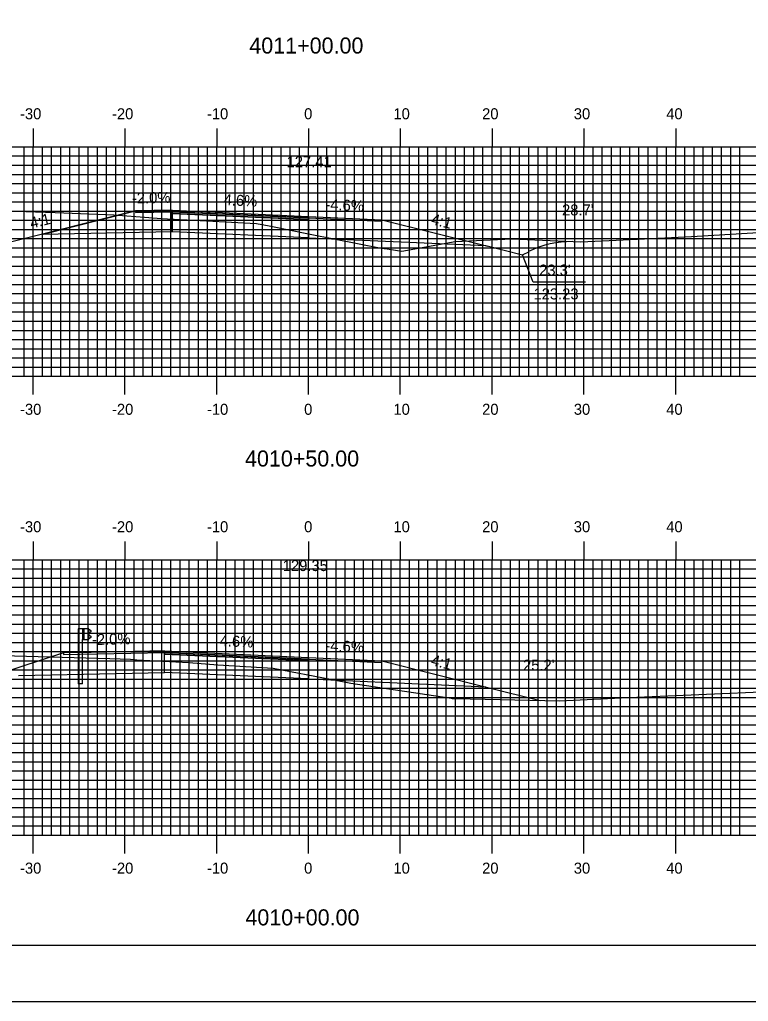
# Model space of a CAD drawing. Extents: x 852540 to 852884, y 364661 to 364881.
# Drawn here: x 852674.8 to 852754.2, y 364661.3 to 364768.2 of the extents above; entities that cross this region are included whole.
import ezdxf

# ---------------------------------------------------------------- set-up
doc = ezdxf.new("R2010")
doc.units = 0
for name, color, linetype in [('ANNOTATION', 7, 'Continuous'), ('BORDER', 7, 'Continuous'), ('D_Guardrail_Beam_Lt', 7, 'Continuous'), ('D_Roadway_Centerline_Text', 7, 'Continuous'), ('D_Roadway_Edge_Shoulder', 7, 'Continuous'), ('D_Roadway_Edge_TW', 7, 'Continuous'), ('D_Roadway_Pavement', 7, 'Continuous'), ('D_Roadway_SlopeLines', 7, 'Continuous'), ('D_Roadway_SubGrade', 7, 'Continuous'), ('D_Text_Standard', 7, 'Continuous'), ('H_V ANNOTATION', 7, 'Continuous'), ('M_Roadway_Centerline', 7, 'Continuous'), ('MAJOR', 7, 'Continuous'), ('MINOR', 7, 'Continuous'), ('PLOT BOUNDARY', 7, 'Continuous'), ('S_Roadway_Centerline', 7, 'Continuous')]:
    doc.layers.add(name, color=color, linetype=linetype)

msp = doc.modelspace()

# ---------------------------------------------------------------- linework, layer by layer
at = {"layer": 'ANNOTATION'}
for points in [[(852725.57, 364743.6), (852729.57, 364742.6), (852730.34, 364742.98)], [(852736.43, 364739.61), (852730.74, 364739.61), (852729.57, 364742.6)]]:
    msp.add_lwpolyline(points, dxfattribs=at)
at = {"layer": 'BORDER'}
msp.add_lwpolyline([(852556.67, 364667.37), (852876.67, 364667.37), (852876.67, 364877.37), (852556.67, 364877.37)], close=True, dxfattribs=at)
at = {"layer": 'D_Guardrail_Beam_Lt'}
for p, q in [((852681.16, 364701.86), (852681.16, 364695.86)), ((852681.63, 364701.86), (852681.16, 364701.86)), ((852682.32, 364701.86), (852681.63, 364701.86)), ((852681.63, 364701.86), (852681.63, 364700.7)), ((852681.69, 364701.86), (852681.69, 364700.7)), ((852681.8, 364701.86), (852681.8, 364700.7)), ((852682.32, 364700.7), (852682.32, 364701.86)), ((852682.32, 364701.78), (852682.39, 364701.77)), ((852682.32, 364701.32), (852682.32, 364701.25)), ((852682.55, 364701.52), (852682.35, 364701.38)), ((852682.35, 364701.18), (852682.55, 364701.05)), ((852682.41, 364701.76), (852682.55, 364701.66)), ((852682.55, 364700.9), (852682.41, 364700.8)), ((852681.63, 364700.7), (852682.32, 364700.7)), ((852681.65, 364695.86), (852681.65, 364700.7)), ((852682.39, 364700.8), (852682.32, 364700.78)), ((852681.65, 364695.86), (852681.16, 364695.86))]:
    msp.add_line(p, q, dxfattribs=at)
for centre, major_axis, start_param, end_param in [((852682.4, 364701.32), (-0.0789, 0), 5.323254, 6.283185), ((852682.4, 364701.25), (-0.0789, 0), 6.283185, 7.243116), ((852682.38, 364701.73), (0.0417, 0), 0.959931, 1.376053), ((852682.5, 364701.59), (0.0877, 0), 5.323254, 7.243116), ((852682.5, 364700.97), (0.0877, 0), 5.323254, 7.243116), ((852682.38, 364700.84), (0.0417, 0), 4.907132, 5.323254)]:
    msp.add_ellipse(centre, major_axis=major_axis, ratio=0.995501, start_param=start_param, end_param=end_param, dxfattribs=at)
at = {"layer": 'D_Roadway_Edge_Shoulder'}
for points in [[(852691.43, 364747.47), (852687.43, 364747.39), (852687.43, 364747.22), (852691.43, 364747.28)], [(852690.59, 364699.44), (852682.59, 364699.28), (852682.59, 364699.28), (852679.59, 364699.22), (852679.59, 364699.05), (852690.59, 364699.25)]]:
    msp.add_lwpolyline(points, close=True, dxfattribs=at)
at = {"layer": 'D_Roadway_Edge_TW'}
for p, q in [((852706.27, 364746.79), (852714.27, 364746.42)), ((852706.27, 364698.72), (852714.27, 364698.35))]:
    msp.add_line(p, q, dxfattribs=at)
for points in [[(852691.43, 364747.47), (852706.27, 364746.79), (852706.27, 364746.62), (852691.43, 364747.28)], [(852690.59, 364699.44), (852706.27, 364698.72), (852706.27, 364698.55), (852690.59, 364699.25)]]:
    msp.add_lwpolyline(points, close=True, dxfattribs=at)
for points in [[(852706.27, 364746.62), (852714.27, 364746.25), (852714.27, 364746.42)], [(852706.27, 364698.55), (852714.27, 364698.19), (852714.27, 364698.35)]]:
    msp.add_lwpolyline(points, dxfattribs=at)
at = {"layer": 'D_Roadway_Pavement'}
for points in [[(852691.43, 364747.28), (852706.27, 364746.62), (852706.27, 364746.46), (852691.43, 364747.12)], [(852690.59, 364699.25), (852706.27, 364698.55), (852706.27, 364698.39), (852690.59, 364699.09)]]:
    msp.add_lwpolyline(points, close=True, dxfattribs=at)
for points in [[(852691.43, 364747.28), (852691.43, 364747.12)], [(852706.27, 364746.62), (852706.27, 364746.46)], [(852706.27, 364746.62), (852706.27, 364746.46)], [(852690.59, 364699.25), (852690.59, 364699.09)], [(852706.27, 364698.55), (852706.27, 364698.39)], [(852706.27, 364698.55), (852706.27, 364698.39)]]:
    msp.add_lwpolyline(points, dxfattribs=at)
at = {"layer": 'D_Roadway_SlopeLines'}
for p, q in [((852679.59, 364699.22), (852636.79, 364685.3)), ((852674.67, 364696.76), (852690.59, 364697.09))]:
    msp.add_line(p, q, dxfattribs=at)
for points in [[(852687.43, 364747.39), (852673.2, 364743.83)], [(852714.27, 364746.42), (852725.8, 364743.54)], [(852714.27, 364698.35), (852725.8, 364695.47), (852731.5, 364694.04)]]:
    msp.add_lwpolyline(points, dxfattribs=at)
msp.add_arc((852734.82, 364734.04), 10, 89.0065, 116.5651, dxfattribs=at)
at = {"layer": 'D_Roadway_SubGrade'}
for p, q in [((852706.27, 364744.46), (852725.57, 364743.6)), ((852706.27, 364696.39), (852725.57, 364695.53))]:
    msp.add_line(p, q, dxfattribs=at)
for points in [[(852691.43, 364745.12), (852677.2, 364744.83), (852687.43, 364747.39), (852687.43, 364747.22), (852691.43, 364747.28), (852691.43, 364747.12)], [(852691.43, 364747.12), (852706.27, 364746.46), (852706.27, 364744.46), (852691.43, 364745.12)], [(852690.59, 364699.09), (852706.27, 364698.39), (852706.27, 364696.39), (852690.59, 364697.09)]]:
    msp.add_lwpolyline(points, close=True, dxfattribs=at)
at = {"layer": 'MAJOR'}
for p, q in [((852676.27, 364756.37), (852676.27, 364754.37)), ((852686.27, 364756.37), (852686.27, 364754.37)), ((852696.27, 364756.37), (852696.27, 364754.37)), ((852706.27, 364756.37), (852706.27, 364754.37)), ((852716.27, 364756.37), (852716.27, 364754.37)), ((852726.27, 364756.37), (852726.27, 364754.37)), ((852736.27, 364756.37), (852736.27, 364754.37)), ((852746.27, 364756.37), (852746.27, 364754.37)), ((852566.27, 364754.37), (852846.27, 364754.37)), ((852566.27, 364754.37), (852846.27, 364754.37)), ((852676.27, 364729.37), (852676.27, 364754.37)), ((852686.27, 364729.37), (852686.27, 364754.37)), ((852696.27, 364729.37), (852696.27, 364754.37)), ((852706.27, 364729.37), (852706.27, 364754.37)), ((852716.27, 364729.37), (852716.27, 364754.37)), ((852726.27, 364729.37), (852726.27, 364754.37)), ((852736.27, 364729.37), (852736.27, 364754.37)), ((852746.27, 364729.37), (852746.27, 364754.37)), ((852566.27, 364749.37), (852846.27, 364749.37)), ((852566.27, 364744.37), (852846.27, 364744.37)), ((852566.27, 364739.37), (852846.27, 364739.37)), ((852566.27, 364734.37), (852846.27, 364734.37)), ((852566.27, 364729.37), (852846.27, 364729.37)), ((852566.27, 364729.37), (852846.27, 364729.37)), ((852676.27, 364727.37), (852676.27, 364729.37)), ((852686.27, 364727.37), (852686.27, 364729.37)), ((852696.27, 364727.37), (852696.27, 364729.37)), ((852706.27, 364727.37), (852706.27, 364729.37)), ((852716.27, 364727.37), (852716.27, 364729.37)), ((852726.27, 364727.37), (852726.27, 364729.37)), ((852736.27, 364727.37), (852736.27, 364729.37)), ((852746.27, 364727.37), (852746.27, 364729.37)), ((852676.27, 364711.37), (852676.27, 364709.37)), ((852686.27, 364711.37), (852686.27, 364709.37)), ((852696.27, 364711.37), (852696.27, 364709.37)), ((852706.27, 364711.37), (852706.27, 364709.37)), ((852716.27, 364711.37), (852716.27, 364709.37)), ((852726.27, 364711.37), (852726.27, 364709.37)), ((852736.27, 364711.37), (852736.27, 364709.37)), ((852746.27, 364711.37), (852746.27, 364709.37)), ((852566.27, 364709.37), (852846.27, 364709.37)), ((852566.27, 364709.37), (852846.27, 364709.37)), ((852676.27, 364679.37), (852676.27, 364709.37)), ((852686.27, 364679.37), (852686.27, 364709.37)), ((852696.27, 364679.37), (852696.27, 364709.37)), ((852706.27, 364679.37), (852706.27, 364709.37)), ((852716.27, 364679.37), (852716.27, 364709.37)), ((852726.27, 364679.37), (852726.27, 364709.37)), ((852736.27, 364679.37), (852736.27, 364709.37)), ((852746.27, 364679.37), (852746.27, 364709.37)), ((852566.27, 364704.37), (852846.27, 364704.37)), ((852566.27, 364699.37), (852846.27, 364699.37)), ((852566.27, 364694.37), (852846.27, 364694.37)), ((852566.27, 364689.37), (852846.27, 364689.37)), ((852566.27, 364684.37), (852846.27, 364684.37)), ((852566.27, 364679.37), (852846.27, 364679.37)), ((852566.27, 364679.37), (852846.27, 364679.37)), ((852676.27, 364677.37), (852676.27, 364679.37)), ((852686.27, 364677.37), (852686.27, 364679.37)), ((852696.27, 364677.37), (852696.27, 364679.37)), ((852706.27, 364677.37), (852706.27, 364679.37)), ((852716.27, 364677.37), (852716.27, 364679.37)), ((852726.27, 364677.37), (852726.27, 364679.37)), ((852736.27, 364677.37), (852736.27, 364679.37)), ((852746.27, 364677.37), (852746.27, 364679.37))]:
    msp.add_line(p, q, dxfattribs=at)
at = {"layer": 'MINOR'}
for p, q in [((852675.27, 364729.37), (852675.27, 364754.37)), ((852677.27, 364729.37), (852677.27, 364754.37)), ((852678.27, 364729.37), (852678.27, 364754.37)), ((852679.27, 364729.37), (852679.27, 364754.37)), ((852680.27, 364729.37), (852680.27, 364754.37)), ((852681.27, 364729.37), (852681.27, 364754.37)), ((852682.27, 364729.37), (852682.27, 364754.37)), ((852683.27, 364729.37), (852683.27, 364754.37)), ((852684.27, 364729.37), (852684.27, 364754.37)), ((852685.27, 364729.37), (852685.27, 364754.37)), ((852687.27, 364729.37), (852687.27, 364754.37)), ((852688.27, 364729.37), (852688.27, 364754.37)), ((852689.27, 364729.37), (852689.27, 364754.37)), ((852690.27, 364729.37), (852690.27, 364754.37)), ((852691.27, 364729.37), (852691.27, 364754.37)), ((852692.27, 364729.37), (852692.27, 364754.37)), ((852693.27, 364729.37), (852693.27, 364754.37)), ((852694.27, 364729.37), (852694.27, 364754.37)), ((852695.27, 364729.37), (852695.27, 364754.37)), ((852697.27, 364729.37), (852697.27, 364754.37)), ((852698.27, 364729.37), (852698.27, 364754.37)), ((852699.27, 364729.37), (852699.27, 364754.37)), ((852700.27, 364729.37), (852700.27, 364754.37)), ((852701.27, 364729.37), (852701.27, 364754.37)), ((852702.27, 364729.37), (852702.27, 364754.37)), ((852703.27, 364729.37), (852703.27, 364754.37)), ((852704.27, 364729.37), (852704.27, 364754.37)), ((852705.27, 364729.37), (852705.27, 364754.37)), ((852707.27, 364729.37), (852707.27, 364754.37)), ((852708.27, 364729.37), (852708.27, 364754.37)), ((852709.27, 364729.37), (852709.27, 364754.37)), ((852710.27, 364729.37), (852710.27, 364754.37)), ((852711.27, 364729.37), (852711.27, 364754.37)), ((852712.27, 364729.37), (852712.27, 364754.37)), ((852713.27, 364729.37), (852713.27, 364754.37)), ((852714.27, 364729.37), (852714.27, 364754.37)), ((852715.27, 364729.37), (852715.27, 364754.37)), ((852717.27, 364729.37), (852717.27, 364754.37)), ((852718.27, 364729.37), (852718.27, 364754.37)), ((852719.27, 364729.37), (852719.27, 364754.37)), ((852720.27, 364729.37), (852720.27, 364754.37)), ((852721.27, 364729.37), (852721.27, 364754.37)), ((852722.27, 364729.37), (852722.27, 364754.37)), ((852723.27, 364729.37), (852723.27, 364754.37)), ((852724.27, 364729.37), (852724.27, 364754.37)), ((852725.27, 364729.37), (852725.27, 364754.37)), ((852727.27, 364729.37), (852727.27, 364754.37)), ((852728.27, 364729.37), (852728.27, 364754.37)), ((852729.27, 364729.37), (852729.27, 364754.37)), ((852730.27, 364729.37), (852730.27, 364754.37)), ((852731.27, 364729.37), (852731.27, 364754.37)), ((852732.27, 364729.37), (852732.27, 364754.37)), ((852733.27, 364729.37), (852733.27, 364754.37)), ((852734.27, 364729.37), (852734.27, 364754.37)), ((852735.27, 364729.37), (852735.27, 364754.37)), ((852737.27, 364729.37), (852737.27, 364754.37)), ((852738.27, 364729.37), (852738.27, 364754.37)), ((852739.27, 364729.37), (852739.27, 364754.37)), ((852740.27, 364729.37), (852740.27, 364754.37)), ((852741.27, 364729.37), (852741.27, 364754.37)), ((852742.27, 364729.37), (852742.27, 364754.37)), ((852743.27, 364729.37), (852743.27, 364754.37)), ((852744.27, 364729.37), (852744.27, 364754.37)), ((852745.27, 364729.37), (852745.27, 364754.37)), ((852747.27, 364729.37), (852747.27, 364754.37)), ((852748.27, 364729.37), (852748.27, 364754.37)), ((852749.27, 364729.37), (852749.27, 364754.37)), ((852750.27, 364729.37), (852750.27, 364754.37)), ((852751.27, 364729.37), (852751.27, 364754.37)), ((852752.27, 364729.37), (852752.27, 364754.37)), ((852753.27, 364729.37), (852753.27, 364754.37)), ((852566.27, 364753.37), (852846.27, 364753.37)), ((852566.27, 364752.37), (852846.27, 364752.37)), ((852566.27, 364751.37), (852846.27, 364751.37)), ((852566.27, 364750.37), (852846.27, 364750.37)), ((852566.27, 364748.37), (852846.27, 364748.37)), ((852566.27, 364747.37), (852846.27, 364747.37)), ((852566.27, 364746.37), (852846.27, 364746.37)), ((852566.27, 364745.37), (852846.27, 364745.37)), ((852566.27, 364743.37), (852846.27, 364743.37)), ((852566.27, 364742.37), (852846.27, 364742.37)), ((852566.27, 364741.37), (852846.27, 364741.37)), ((852566.27, 364740.37), (852846.27, 364740.37)), ((852566.27, 364738.37), (852846.27, 364738.37)), ((852566.27, 364737.37), (852846.27, 364737.37)), ((852566.27, 364736.37), (852846.27, 364736.37)), ((852566.27, 364735.37), (852846.27, 364735.37)), ((852566.27, 364733.37), (852846.27, 364733.37)), ((852566.27, 364732.37), (852846.27, 364732.37)), ((852566.27, 364731.37), (852846.27, 364731.37)), ((852566.27, 364730.37), (852846.27, 364730.37)), ((852566.27, 364708.37), (852846.27, 364708.37)), ((852675.27, 364679.37), (852675.27, 364709.37)), ((852677.27, 364679.37), (852677.27, 364709.37)), ((852678.27, 364679.37), (852678.27, 364709.37)), ((852679.27, 364679.37), (852679.27, 364709.37)), ((852680.27, 364679.37), (852680.27, 364709.37)), ((852681.27, 364679.37), (852681.27, 364709.37)), ((852682.27, 364679.37), (852682.27, 364709.37)), ((852683.27, 364679.37), (852683.27, 364709.37)), ((852684.27, 364679.37), (852684.27, 364709.37)), ((852685.27, 364679.37), (852685.27, 364709.37)), ((852687.27, 364679.37), (852687.27, 364709.37)), ((852688.27, 364679.37), (852688.27, 364709.37)), ((852689.27, 364679.37), (852689.27, 364709.37)), ((852690.27, 364679.37), (852690.27, 364709.37)), ((852691.27, 364679.37), (852691.27, 364709.37)), ((852692.27, 364679.37), (852692.27, 364709.37)), ((852693.27, 364679.37), (852693.27, 364709.37)), ((852694.27, 364679.37), (852694.27, 364709.37)), ((852695.27, 364679.37), (852695.27, 364709.37)), ((852697.27, 364679.37), (852697.27, 364709.37)), ((852698.27, 364679.37), (852698.27, 364709.37)), ((852699.27, 364679.37), (852699.27, 364709.37)), ((852700.27, 364679.37), (852700.27, 364709.37)), ((852701.27, 364679.37), (852701.27, 364709.37)), ((852702.27, 364679.37), (852702.27, 364709.37)), ((852703.27, 364679.37), (852703.27, 364709.37)), ((852704.27, 364679.37), (852704.27, 364709.37)), ((852705.27, 364679.37), (852705.27, 364709.37)), ((852707.27, 364679.37), (852707.27, 364709.37)), ((852708.27, 364679.37), (852708.27, 364709.37)), ((852709.27, 364679.37), (852709.27, 364709.37)), ((852710.27, 364679.37), (852710.27, 364709.37)), ((852711.27, 364679.37), (852711.27, 364709.37)), ((852712.27, 364679.37), (852712.27, 364709.37)), ((852713.27, 364679.37), (852713.27, 364709.37)), ((852714.27, 364679.37), (852714.27, 364709.37)), ((852715.27, 364679.37), (852715.27, 364709.37)), ((852717.27, 364679.37), (852717.27, 364709.37)), ((852718.27, 364679.37), (852718.27, 364709.37)), ((852719.27, 364679.37), (852719.27, 364709.37)), ((852720.27, 364679.37), (852720.27, 364709.37)), ((852721.27, 364679.37), (852721.27, 364709.37)), ((852722.27, 364679.37), (852722.27, 364709.37)), ((852723.27, 364679.37), (852723.27, 364709.37)), ((852724.27, 364679.37), (852724.27, 364709.37)), ((852725.27, 364679.37), (852725.27, 364709.37)), ((852727.27, 364679.37), (852727.27, 364709.37)), ((852728.27, 364679.37), (852728.27, 364709.37)), ((852729.27, 364679.37), (852729.27, 364709.37)), ((852730.27, 364679.37), (852730.27, 364709.37)), ((852731.27, 364679.37), (852731.27, 364709.37)), ((852732.27, 364679.37), (852732.27, 364709.37)), ((852733.27, 364679.37), (852733.27, 364709.37)), ((852734.27, 364679.37), (852734.27, 364709.37)), ((852735.27, 364679.37), (852735.27, 364709.37)), ((852737.27, 364679.37), (852737.27, 364709.37)), ((852738.27, 364679.37), (852738.27, 364709.37)), ((852739.27, 364679.37), (852739.27, 364709.37)), ((852740.27, 364679.37), (852740.27, 364709.37)), ((852741.27, 364679.37), (852741.27, 364709.37)), ((852742.27, 364679.37), (852742.27, 364709.37)), ((852743.27, 364679.37), (852743.27, 364709.37)), ((852744.27, 364679.37), (852744.27, 364709.37)), ((852745.27, 364679.37), (852745.27, 364709.37)), ((852747.27, 364679.37), (852747.27, 364709.37)), ((852748.27, 364679.37), (852748.27, 364709.37)), ((852749.27, 364679.37), (852749.27, 364709.37)), ((852750.27, 364679.37), (852750.27, 364709.37)), ((852751.27, 364679.37), (852751.27, 364709.37)), ((852752.27, 364679.37), (852752.27, 364709.37)), ((852753.27, 364679.37), (852753.27, 364709.37)), ((852566.27, 364707.37), (852846.27, 364707.37)), ((852566.27, 364706.37), (852846.27, 364706.37)), ((852566.27, 364705.37), (852846.27, 364705.37)), ((852566.27, 364703.37), (852846.27, 364703.37)), ((852566.27, 364702.37), (852846.27, 364702.37)), ((852566.27, 364701.37), (852846.27, 364701.37)), ((852566.27, 364700.37), (852846.27, 364700.37)), ((852566.27, 364698.37), (852846.27, 364698.37)), ((852566.27, 364697.37), (852846.27, 364697.37)), ((852566.27, 364696.37), (852846.27, 364696.37)), ((852566.27, 364695.37), (852846.27, 364695.37)), ((852566.27, 364693.37), (852846.27, 364693.37)), ((852566.27, 364692.37), (852846.27, 364692.37)), ((852566.27, 364691.37), (852846.27, 364691.37)), ((852566.27, 364690.37), (852846.27, 364690.37)), ((852566.27, 364688.37), (852846.27, 364688.37)), ((852566.27, 364687.37), (852846.27, 364687.37)), ((852566.27, 364686.37), (852846.27, 364686.37)), ((852566.27, 364685.37), (852846.27, 364685.37)), ((852566.27, 364683.37), (852846.27, 364683.37)), ((852566.27, 364682.37), (852846.27, 364682.37)), ((852566.27, 364681.37), (852846.27, 364681.37)), ((852566.27, 364680.37), (852846.27, 364680.37))]:
    msp.add_line(p, q, dxfattribs=at)
at = {"layer": 'PLOT BOUNDARY'}
msp.add_lwpolyline([(852540.48, 364661.25), (852880.48, 364661.25), (852880.48, 364881.25), (852540.48, 364881.25)], close=True, dxfattribs=at)
at = {"layer": 'S_Roadway_Centerline'}
for points in [[(852671.2, 364747.48), (852678.68, 364747.21), (852679.61, 364747.18), (852685.07, 364746.97), (852688.86, 364746.66), (852690.23, 364746.57), (852695.17, 364746.3), (852700.61, 364746), (852701.98, 364745.77), (852706.46, 364744.84), (852714.19, 364743.34), (852714.85, 364743.24), (852716.45, 364743.01), (852722.25, 364744.06), (852728.43, 364744.33), (852735.93, 364744), (852743.63, 364744.39), (852747.98, 364744.6), (852766.82, 364745.71)], [(852672.92, 364698.93), (852684.63, 364698.62), (852686.87, 364698.54), (852687.55, 364698.48), (852693.24, 364698.16), (852696.39, 364697.92), (852702.41, 364697.56), (852708.86, 364696.34), (852710.89, 364695.94), (852720.88, 364694.45), (852721.82, 364694.28), (852721.9, 364694.26), (852722.25, 364694.25), (852733.64, 364694), (852740.34, 364694.32), (852757.27, 364695.05)]]:
    msp.add_lwpolyline(points, dxfattribs=at)

# ---------------------------------------------------------------- texts
at = {"layer": 'ANNOTATION'}
for s, rotation, p in [('-2.0%', 1.1458, (852687.04, 364748.18)), ('4.6%', 357.3663, (852697, 364748.02)), ('-4.6%', 357.3663, (852708.09, 364747.51)), ('4:1', 14.0362, (852676.08, 364745.45)), ('4:1', 345.9638, (852719.54, 364745.96)), ('-2.0%', 1.1458, (852682.69, 364700.08)), ('4.6%', 357.3663, (852696.57, 364699.97)), ('-4.6%', 357.3663, (852708.09, 364699.44)), ('4:1', 345.9638, (852719.54, 364697.9))]:
    msp.add_text(s, height=1.2, rotation=rotation, dxfattribs=at).set_placement(p)
for s, p in [("23.3' ", (852731.4, 364740.34)), ('123.23', (852730.78, 364737.74))]:
    msp.add_text(s, height=1.2, dxfattribs=at).set_placement(p)
at = {"layer": 'D_Roadway_Centerline_Text'}
for s, p in [('127.41', (852703.88, 364752.15)), ('129.35', (852703.46, 364708.14))]:
    msp.add_text(s, height=1.2, dxfattribs=at).set_placement(p)
at = {"layer": 'D_Text_Standard'}
for s, p in [("28.7'", (852733.89, 364746.89)), ("25.2'", (852729.64, 364697.29))]:
    msp.add_text(s, height=1.2, dxfattribs=at).set_placement(p)
at = {"layer": 'H_V ANNOTATION'}
for s, height, p in [('4011+00.00', 1.75, (852699.82, 364764.53)), ('-30', 1.2, (852674.84, 364757.37)), ('-20', 1.2, (852684.86, 364757.37)), ('-10', 1.2, (852695.2, 364757.37)), ('0', 1.2, (852705.79, 364757.37)), ('10', 1.2, (852715.52, 364757.37)), ('20', 1.2, (852725.18, 364757.37)), ('30', 1.2, (852735.17, 364757.37)), ('40', 1.2, (852745.24, 364757.37)), ('-30', 1.2, (852674.84, 364725.17)), ('-20', 1.2, (852684.86, 364725.17)), ('-10', 1.2, (852695.2, 364725.17)), ('0', 1.2, (852705.79, 364725.17)), ('10', 1.2, (852715.52, 364725.17)), ('20', 1.2, (852725.18, 364725.17)), ('30', 1.2, (852735.17, 364725.17)), ('40', 1.2, (852745.24, 364725.17)), ('4010+50.00', 1.75, (852699.35, 364719.53)), ('-30', 1.2, (852674.84, 364712.37)), ('-20', 1.2, (852684.86, 364712.37)), ('-10', 1.2, (852695.2, 364712.37)), ('0', 1.2, (852705.79, 364712.37)), ('10', 1.2, (852715.52, 364712.37)), ('20', 1.2, (852725.18, 364712.37)), ('30', 1.2, (852735.17, 364712.37)), ('40', 1.2, (852745.24, 364712.37)), ('-30', 1.2, (852674.84, 364675.17)), ('-20', 1.2, (852684.86, 364675.17)), ('-10', 1.2, (852695.2, 364675.17)), ('0', 1.2, (852705.79, 364675.17)), ('10', 1.2, (852715.52, 364675.17)), ('20', 1.2, (852725.18, 364675.17)), ('30', 1.2, (852735.17, 364675.17)), ('40', 1.2, (852745.24, 364675.17)), ('4010+00.00', 1.75, (852699.39, 364669.53))]:
    msp.add_text(s, height=height, dxfattribs=at).set_placement(p)
at = {"layer": 'M_Roadway_Centerline'}
for s, p in [('C', (852685.07, 364746.97)), ('L', (852685.07, 364746.96)), ('C', (852686.86, 364698.54)), ('L', (852686.87, 364698.53))]:
    msp.add_text(s, height=0.0146, dxfattribs=at).set_placement(p)

doc.saveas('drawing.dxf')
